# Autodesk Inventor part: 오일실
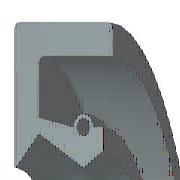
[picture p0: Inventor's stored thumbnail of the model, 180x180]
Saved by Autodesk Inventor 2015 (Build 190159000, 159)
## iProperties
Created: 2015-11
Part Number: 오일실
Material: 고무
Description: 오일-실
Document SubType Name: Modeling
Standard: KS B 2804
Designer: mdu
Standards Organization: KS
Language: ko-KR
Size Designation: D - 10 20 7
Categories: <MemberInstance><Categories><Category DisplayName="샤프트 부품" InternalName="7f7aeb1f-a693-4053-b835-cee3144e0d98" Mnemonic="SHFT"><Category DisplayName="실링" Intern
Density: 0.93 g/cm^3
Appearance: 고무 - 검은색 - 버전 1.1
IsCustomPart: 0
Author: mdu
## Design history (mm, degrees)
revolve "본체" stored, may be unused: angle "d17" = 90 deg
revolve "스프링1" stored, may be unused: angle "d18" = 90 deg
body "Solid1"
sketch "스케치1"
  geometry: L1 (0, 10)-(7, 10); L2 (7, 8.25)-(1.75, 8.25); L3 (1.75, 6.75)-(4.9, 5); L4 (4.9, 5)-(0, 5); L5 (0, 0)-(9.586, 0) reference; L6 (4.9, 5)-(6.3, 5.875); L7 (0, 18)-(0, -3) reference; L8 (-1.941, 0)-(11.507, 0) reference; L9 (4.2, 7.1)-(1.75, 7.59); L10 (1.75, 7.59)-(1.75, 8.25); L11 (0, 10)-(0, 5.088); L12 (4.9, 5)-(0, 5); L13 (1.75, 6.75)-(0.152, 5.028); L14 (7, 10)-(7, 8.25); L15 (5.6, 7.1)-(6.3, 7.1); L16 (6.3, 7.1)-(6.3, 5.875); C1 r 0.455 at (4.9, 7.1); A1 r 0.7 centre (4.9, 7.1) between (5.6, 7.1) and (4.2, 7.1); A2 r 0.088 centre (0.088, 5.088) between (0, 5.088) and (0.152, 5.028); 1 further point
  constraints: 28 end point, 5 horizontal alignment, 5 point on line, 4 point on circle, 4 vertical alignment, 3 centre point, 3 tangent, 2 collinear, 2 horizontal, 2 perpendicular, 1 coincident, 1 parallel
  dimensions: "d0" = 20 diameter of L1 L5 (= SD2); "d1" = 1.75 distance of L1.end L2.start (= SD); "d2" = 0.91 diameter of C1 (= SPDI); "d3" = 1.4 diameter of A1 (= SPDA); "d4" = 10 diameter of L3.end L5 (= NND); "d5" = 13.5 diameter of L3.start L5 (= TKDM); "d7" = 15.18 diameter of L9.end L5 (= TKDM + 0.24 x SWDT); "d8" = 1.75 distance between parallel lines of L11 L10 (= SD); "d9" = 4.9 distance from line of L11 C1.centre (= SPDST); "d10" = 14.2 diameter of C1.centre L5 (= HLDM); "d11" = 0.0875 radius of A2 (= 0.25 x LAB); "d12" = 6.3 distance between parallel lines of L11 L16 (= SDI); "d13" = 11.75 diameter of L6.end L5 (= ABDM); "d14" = 7 distance from line of L11 L1.end (= SWDT)
fillet "모깎기1" dims "d6" = 0.3 (= RR)
other parameters: "SD2" = 20 [user parameter; used in 1 equation term], "SWDT" = 7 [user parameter; used in 2 equation terms], "RR" = 0.3 [user parameter; used in 1 equation term], "SD" = 1.75 [user parameter; used in 2 equation terms], "NND" = 10 [user parameter; used in 1 equation term], "SPDA" = 1.4 [user parameter; used in 1 equation term], "SPDI" = 0.91 [user parameter; used in 1 equation term], "TKDM" = 13.5 [user parameter; used in 2 equation terms], "HLDM" = 14.2 [user parameter; used in 1 equation term], "ABDM" = 11.75 [user parameter; used in 1 equation term], "SDI" = 6.3 [user parameter; used in 1 equation term], "SPDST" = 4.9 [user parameter; used in 1 equation term], "LAB" = 0.35 [user parameter; used in 1 equation term], "d15" = 0, "d16" = 0, "d19" = 0
